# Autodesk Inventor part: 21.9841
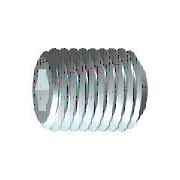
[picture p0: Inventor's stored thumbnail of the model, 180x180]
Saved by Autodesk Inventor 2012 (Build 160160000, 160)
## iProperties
IsCustomPart: 1
Created: 2006-02
Part Number: 21.9841
Material: Steel, Mild
Description: M4x5 Set Screw With Flat Point
Document SubType Name: Modeling
Standard: DIN 913
Designer: Andy Moles
Standards Organization: DIN
Language: en-US
Size Designation: M4 x 5
Categories: <MemberInstance><Categories><Category DisplayName="Fasteners" InternalName="e4da775c-781d-43d5-af7c-5136215cf5a6" Mnemonic="FSTN"><Category DisplayName="Bolts"
Density: 7.86 g/cm^3
Mass: 0.418265 g
Surface Area: 0.908613 cm^2
Volume: 0.0532144 cm^3
Vendor: S
Author: Andy Moles
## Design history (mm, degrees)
revolve "Body" stored, may be unused: angle "d6" = 90 deg
sketch "Sketch2"
  geometry: L1 (-0.577, 1)-(0.577, 1); L2 (0.577, 1)-(1.155, 0); L3 (1.155, 0)-(0.577, -1); L4 (0.577, -1)-(-0.577, -1); L5 (-0.577, -1)-(-1.155, 0); L6 (-1.155, 0)-(-0.577, 1); 3 further points
  constraints: 12 end point, 1 coincident, 1 horizontal, 13 other
extrude "Slot" join sketch "Sketch2" taper "d7" = 0 deg; stored distance "d21" = 10
workaxis "Work Axis1"
workplane "Work Plane1"
body "Solid1"
feature "Thread" dims "d8" = 5 (= NLG), "d9" = 0
chamfer "Chamfer1" distance "d10" = 0.42941 (= -0.5 x GD1 + 0.5 x NND); stored, may be unused: angle "d11" = 60 deg (= FAWI), second distance "d34" = 0.42941 (= -0.5 x GD1 + 0.5 x NND)
chamfer "Chamfer2" distance "d12" = 0.42941 (= -0.5 x GD1 + 0.5 x NND); stored, may be unused: angle "d13" = 60 deg (= FAWI), second distance "d35" = 0.42941 (= -0.5 x GD1 + 0.5 x NND)
sketch "Sketch1"
  geometry: L1 (0, 0)-(2.833, 0); L2 (5, 1.155)-(5, 2); L3 (5, 2)-(0, 2); L4 (5, 1.155)-(3.5, 1.155); L5 (3.5, 1.155)-(2.833, 0); L6 (0, -0.2)-(0, 2.6) reference; L7 (0, 2)-(0, 0)
  constraints: 13 end point, 3 parallel, 1 collinear, 1 perpendicular, 1 point on line
  dimensions: "d0" = 1.5 distance of L2.start L4.end (= INTI); "d1" = 60 deg angle of L5 L1; "d2" = 4 diameter of L3 L1 (= NND); "d3" = 2.3094 diameter of L4 L1 (= 1.1547 x SW); "d5" = 5 distance from line of L2 L3.end (= NLG)
other parameters: "NND" = 4 [user parameter; used in 5 equation terms], "NLG" = 5 [user parameter; used in 2 equation terms], "INTI" = 1.5 [user parameter; used in 1 equation term], "FAWI" = 60 deg [user parameter; used in 2 equation terms], "SW" = 2 [user parameter; used in 2 equation terms], "GD1" = 3.14117 (= THREADDIA - 1.2269 x PTC) [user parameter; used in 4 equation terms], "d4" = 0, "SPD" = 2.5 [user parameter], "d33" = 0, "d36" = 0, "GUL" = 0.42941 (= 0.61345 x PTC) [user parameter], "TPU" = 14.28571 (computed from PTC) [user parameter], "TOA" = 30 deg [user parameter], "THREADDIA" = 4 [user parameter; used in 1 equation term], "PTC" = 0.7 [user parameter; used in 4 equation terms], "FAWI1" = 45 deg [user parameter], "GAL" = 0.42941 (= 0.61345 x PTC) [user parameter], "E0" = 2.31 (= 1.155 x SW) [user parameter]
